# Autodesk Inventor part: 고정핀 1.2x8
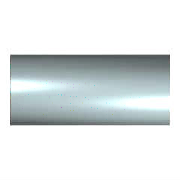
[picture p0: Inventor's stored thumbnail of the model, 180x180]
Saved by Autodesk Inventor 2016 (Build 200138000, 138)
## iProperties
IsCustomPart: 1
Created: 2012-02
Part Number: 고정핀 1.2x8
Material: 강철, 연강
Description: 평행 핀
Document SubType Name: Modeling
Standard: KS B 1320
Designer: P15F
Standards Organization: KS
Language: ko-KR
Size Designation: C 1.2 x  8
Categories: <MemberInstance><Categories><Category DisplayName="조임쇠" InternalName="e4da775c-781d-43d5-af7c-5136215cf5a6" Mnemonic="FSTN"><Category DisplayName="핀" InternalNa
Density: 1 g/cm^3
Appearance: 노란색
Author: P15F
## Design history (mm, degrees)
sketch "스케치1"
  geometry: C1 r 0.6 at (0, 0); 1 further point
  constraints: 1 centre point, 1 coincident
  dimensions: "d1" = 1.2 diameter of C1 (= NND)
extrude "본체" new body sketch "스케치1" distance "d2" = 8 (= NLG); taper "d3" = 0 deg
node "작업 평면1"
body "Solid1"
other parameters: "NND" = 1.2 [user parameter; used in 1 equation term], "NLG" = 8 [user parameter; used in 1 equation term], "d8" = 0, "d9" = 0, "d10" = 0
